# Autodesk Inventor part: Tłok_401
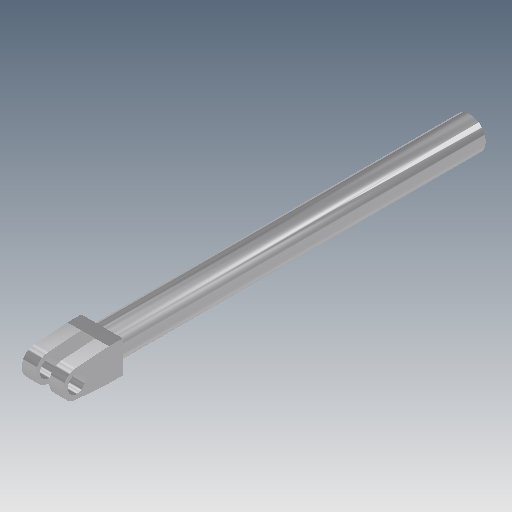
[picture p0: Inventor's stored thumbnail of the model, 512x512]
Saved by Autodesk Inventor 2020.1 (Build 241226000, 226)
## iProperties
Created: 2006-06
Part Number: Tłok_401
Document SubType Name: Modeling
Designer: F.Stasiak
Density: 1 g/cm^3
Material: Ogólny
Appearance: Chrom
Manager: www.cadconsulting.pl
Company: Fabian Stasiak CAD Consulting
Author: F.Stasiak
Subject: Zbiór ćwiczeń. Autodesk Inventor 2020. Kurs podstawowy
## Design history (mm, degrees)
sketch "Szkic1"
  geometry: C1 r 17.5 at (0, 0); 1 further point
  constraints: 1 centre point, 1 coincident
  dimensions: "d0" = 35 diameter of C1
extrude "Wyciągnięcie proste1" new body sketch "Szkic1" distance "d1" = 400; taper "d2" = 0 deg
sketch "Szkic2"
  geometry: L1 (-22.5, 17.5)-(22.5, 17.5); L2 (22.5, 17.5)-(22.5, -17.5); L3 (22.5, -17.5)-(-22.5, -17.5); L4 (-22.5, -17.5)-(-22.5, 17.5); L5 (0, 17.5)-(0, -17.5); C1 r 17.5 at (0, 0) reference; 1 further point
  constraints: 10 end point, 3 midpoint, 2 parallel, 2 tangent, 1 coincident, 1 horizontal, 1 perpendicular
  dimensions: "d3" = 45 distance of L2.end L3.end
extrude "Wyciągnięcie proste2" join sketch "Szkic2" distance "d4" = 15; taper "d5" = 0 deg
sketch "Szkic3"
  geometry: L1 (-15, 35)-(-15, 0) reference; L2 (-15, 35)-(-51.053, 32.463); L3 (-51.053, 2.537)-(-15, 0); L4 (-50, 17.5)-(-15, 17.5); C1 r 10 at (-50, 17.5); A1 r 15 centre (-50, 17.5) between (-51.053, 32.463) and (-51.053, 2.537)
  constraints: 6 end point, 2 centre point, 2 point on circle, 2 tangent, 1 coincident, 1 horizontal, 1 midpoint
  dimensions: "d6" = 15 radius of A1; "d7" = 35 distance of L4.start L4.end; "d8" = 20 diameter of C1
extrude "Wyciągnięcie proste3" join sketch "Szkic3" distance "d9" = 15; taper "d10" = 0 deg
node "Płaszczyzna konstrukcyjna1"
mirror "Lustro1"
node "Bryła1"
node "Korpusy bryłowe"
node "Korpusy powierzchniowe"
